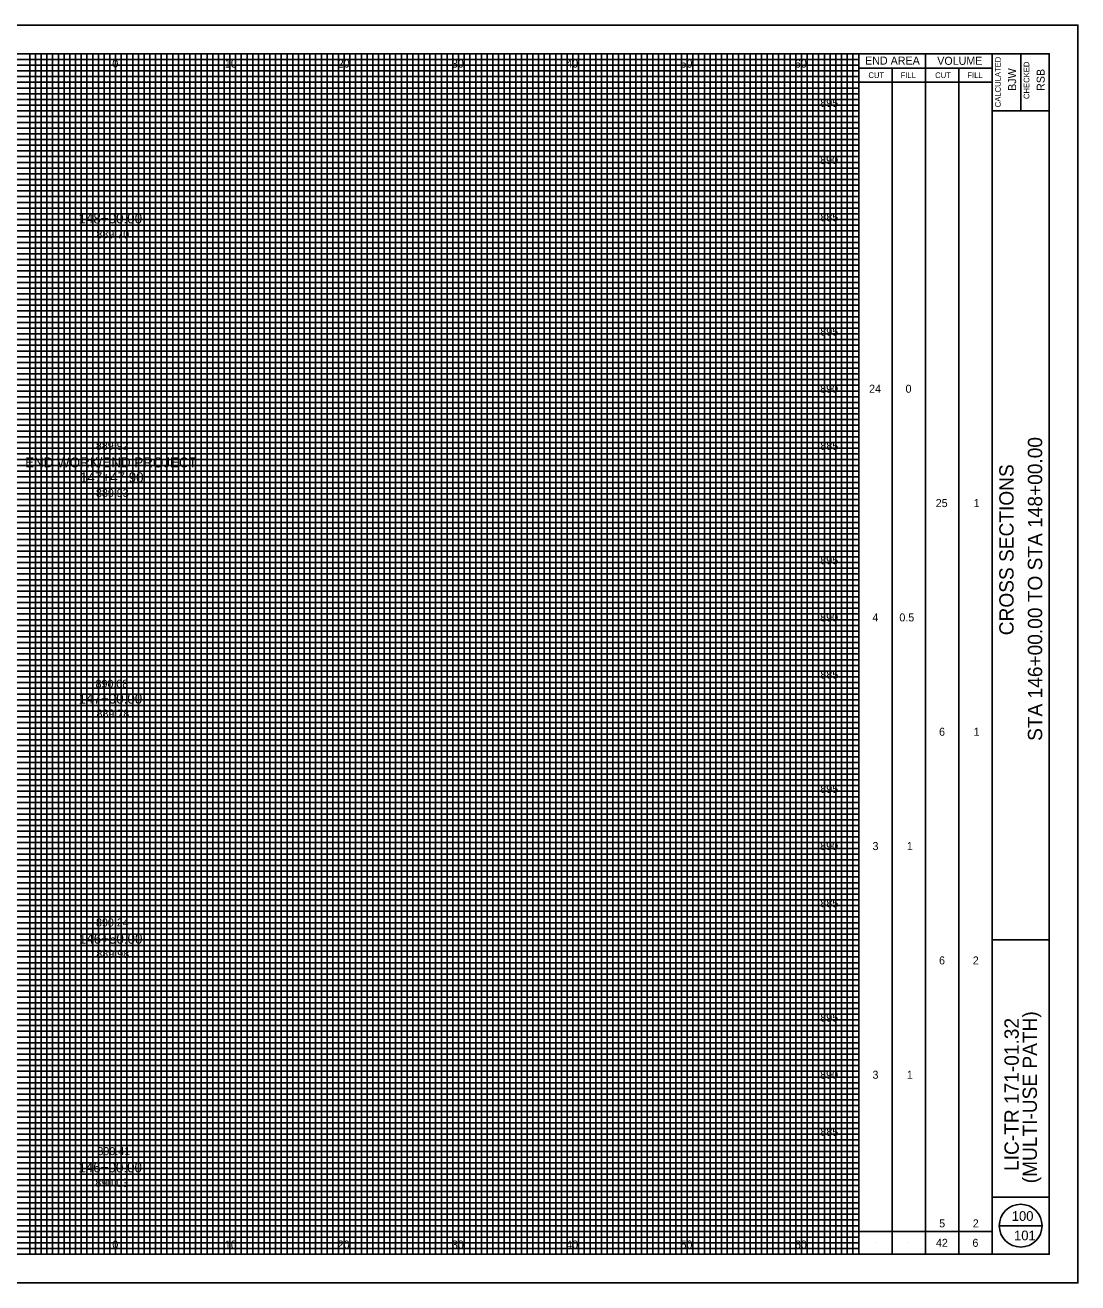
# Model space of a CAD drawing. Extents: x -10 to 160, y -2 to 3672.
# Drawn here: x 67.9 to 160, y 3562.5 to 3672.5 of the extents above; entities that cross this region are included whole.
import ezdxf

# ---------------------------------------------------------------- set-up
doc = ezdxf.new("R2010")
doc.units = 0
for name, color, linetype in [('SH_Border', 7, 'Continuous'), ('SH_Cut_Line', 7, 'Continuous'), ('SH_Data', 7, 'Continuous'), ('SH_Major_Grid_Line', 7, 'Continuous'), ('SH_Minor_Grid_Line', 7, 'Continuous'), ('SH_Text', 7, 'Continuous'), ('TX_P_10', 7, 'Continuous'), ('TX_X_10', 7, 'Continuous')]:
    doc.layers.add(name, color=color, linetype=linetype)

msp = doc.modelspace()

# ---------------------------------------------------------------- linework, layer by layer
at = {"layer": 'SH_Border'}
for p, q in [((152.5, 3565), (152.5, 3670)), ((155, 3670), (155, 3665)), ((152.5, 3665), (157.5, 3665)), ((152.5, 3592.5), (157.5, 3592.5)), ((152.5, 3570), (157.5, 3570))]:
    msp.add_line(p, q, dxfattribs=at)
msp.add_lwpolyline([(0, 3670), (157.5, 3670), (157.5, 3565), (0, 3565)], close=True, dxfattribs=at)
at = {"layer": 'SH_Cut_Line'}
msp.add_lwpolyline([(-10, 3562.5), (160, 3562.5), (160, 3672.5), (-10, 3672.5)], close=True, dxfattribs=at)
at = {"layer": 'SH_Data'}
for p, q in [((140.83, 3565), (140.83, 3670)), ((146.67, 3565), (146.67, 3670)), ((140.83, 3668.75), (152.5, 3668.75)), ((143.75, 3565), (143.75, 3668.75)), ((149.58, 3565), (149.58, 3668.75)), ((140.83, 3667.5), (152.5, 3667.5)), ((153.12, 3567.5), (156.88, 3567.5)), ((140.83, 3567), (152.5, 3567)), ((142.29, 3566), (142.29, 3566)), ((145.21, 3566), (145.21, 3566)), ((148.12, 3566), (148.12, 3566)), ((151.04, 3566), (151.04, 3566))]:
    msp.add_line(p, q, dxfattribs=at)
msp.add_circle((155, 3567.5), 1.87, dxfattribs=at)
at = {"layer": 'SH_Major_Grid_Line'}
for p, q in [((70.83, 3565), (70.83, 3670)), ((75.83, 3565), (75.83, 3670)), ((80.83, 3565), (80.83, 3670)), ((85.83, 3565), (85.83, 3670)), ((90.83, 3565), (90.83, 3670)), ((95.83, 3565), (95.83, 3670)), ((100.83, 3565), (100.83, 3670)), ((105.83, 3565), (105.83, 3670)), ((110.83, 3565), (110.83, 3670)), ((115.83, 3565), (115.83, 3670)), ((120.83, 3565), (120.83, 3670)), ((125.83, 3565), (125.83, 3670)), ((130.83, 3565), (130.83, 3670)), ((135.83, 3565), (135.83, 3670)), ((5.83, 3665), (140.83, 3665)), ((5.83, 3660), (140.83, 3660)), ((5.83, 3655), (140.83, 3655)), ((5.83, 3650), (140.83, 3650)), ((5.83, 3645), (140.83, 3645)), ((5.83, 3640), (140.83, 3640)), ((5.83, 3635), (140.83, 3635)), ((5.83, 3630), (140.83, 3630)), ((5.83, 3625), (140.83, 3625)), ((5.83, 3620), (140.83, 3620)), ((5.83, 3615), (140.83, 3615)), ((5.83, 3610), (140.83, 3610)), ((5.83, 3605), (140.83, 3605)), ((5.83, 3600), (140.83, 3600)), ((5.83, 3595), (140.83, 3595)), ((5.83, 3590), (140.83, 3590)), ((5.83, 3585), (140.83, 3585)), ((5.83, 3580), (140.83, 3580)), ((5.83, 3575), (140.83, 3575)), ((5.83, 3570), (140.83, 3570))]:
    msp.add_line(p, q, dxfattribs=at)
at = {"layer": 'SH_Minor_Grid_Line'}
for p, q in [((68.33, 3565), (68.33, 3670)), ((68.83, 3565), (68.83, 3670)), ((69.33, 3565), (69.33, 3670)), ((69.83, 3565), (69.83, 3670)), ((70.33, 3565), (70.33, 3670)), ((71.33, 3565), (71.33, 3670)), ((71.83, 3565), (71.83, 3670)), ((72.33, 3565), (72.33, 3670)), ((72.83, 3565), (72.83, 3670)), ((73.33, 3565), (73.33, 3670)), ((73.83, 3565), (73.83, 3670)), ((74.33, 3565), (74.33, 3670)), ((74.83, 3565), (74.83, 3670)), ((75.33, 3565), (75.33, 3670)), ((76.33, 3565), (76.33, 3670)), ((76.83, 3565), (76.83, 3670)), ((77.33, 3565), (77.33, 3670)), ((77.83, 3565), (77.83, 3670)), ((78.33, 3565), (78.33, 3670)), ((78.83, 3565), (78.83, 3670)), ((79.33, 3565), (79.33, 3670)), ((79.83, 3565), (79.83, 3670)), ((80.33, 3565), (80.33, 3670)), ((81.33, 3565), (81.33, 3670)), ((81.83, 3565), (81.83, 3670)), ((82.33, 3565), (82.33, 3670)), ((82.83, 3565), (82.83, 3670)), ((83.33, 3565), (83.33, 3670)), ((83.83, 3565), (83.83, 3670)), ((84.33, 3565), (84.33, 3670)), ((84.83, 3565), (84.83, 3670)), ((85.33, 3565), (85.33, 3670)), ((86.33, 3565), (86.33, 3670)), ((86.83, 3565), (86.83, 3670)), ((87.33, 3565), (87.33, 3670)), ((87.83, 3565), (87.83, 3670)), ((88.33, 3565), (88.33, 3670)), ((88.83, 3565), (88.83, 3670)), ((89.33, 3565), (89.33, 3670)), ((89.83, 3565), (89.83, 3670)), ((90.33, 3565), (90.33, 3670)), ((91.33, 3565), (91.33, 3670)), ((91.83, 3565), (91.83, 3670)), ((92.33, 3565), (92.33, 3670)), ((92.83, 3565), (92.83, 3670)), ((93.33, 3565), (93.33, 3670)), ((93.83, 3565), (93.83, 3670)), ((94.33, 3565), (94.33, 3670)), ((94.83, 3565), (94.83, 3670)), ((95.33, 3565), (95.33, 3670)), ((96.33, 3565), (96.33, 3670)), ((96.83, 3565), (96.83, 3670)), ((97.33, 3565), (97.33, 3670)), ((97.83, 3565), (97.83, 3670)), ((98.33, 3565), (98.33, 3670)), ((98.83, 3565), (98.83, 3670)), ((99.33, 3565), (99.33, 3670)), ((99.83, 3565), (99.83, 3670)), ((100.33, 3565), (100.33, 3670)), ((101.33, 3565), (101.33, 3670)), ((101.83, 3565), (101.83, 3670)), ((102.33, 3565), (102.33, 3670)), ((102.83, 3565), (102.83, 3670)), ((103.33, 3565), (103.33, 3670)), ((103.83, 3565), (103.83, 3670)), ((104.33, 3565), (104.33, 3670)), ((104.83, 3565), (104.83, 3670)), ((105.33, 3565), (105.33, 3670)), ((106.33, 3565), (106.33, 3670)), ((106.83, 3565), (106.83, 3670)), ((107.33, 3565), (107.33, 3670)), ((107.83, 3565), (107.83, 3670)), ((108.33, 3565), (108.33, 3670)), ((108.83, 3565), (108.83, 3670)), ((109.33, 3565), (109.33, 3670)), ((109.83, 3565), (109.83, 3670)), ((110.33, 3565), (110.33, 3670)), ((111.33, 3565), (111.33, 3670)), ((111.83, 3565), (111.83, 3670)), ((112.33, 3565), (112.33, 3670)), ((112.83, 3565), (112.83, 3670)), ((113.33, 3565), (113.33, 3670)), ((113.83, 3565), (113.83, 3670)), ((114.33, 3565), (114.33, 3670)), ((114.83, 3565), (114.83, 3670)), ((115.33, 3565), (115.33, 3670)), ((116.33, 3565), (116.33, 3670)), ((116.83, 3565), (116.83, 3670)), ((117.33, 3565), (117.33, 3670)), ((117.83, 3565), (117.83, 3670)), ((118.33, 3565), (118.33, 3670)), ((118.83, 3565), (118.83, 3670)), ((119.33, 3565), (119.33, 3670)), ((119.83, 3565), (119.83, 3670)), ((120.33, 3565), (120.33, 3670)), ((121.33, 3565), (121.33, 3670)), ((121.83, 3565), (121.83, 3670)), ((122.33, 3565), (122.33, 3670)), ((122.83, 3565), (122.83, 3670)), ((123.33, 3565), (123.33, 3670)), ((123.83, 3565), (123.83, 3670)), ((124.33, 3565), (124.33, 3670)), ((124.83, 3565), (124.83, 3670)), ((125.33, 3565), (125.33, 3670)), ((126.33, 3565), (126.33, 3670)), ((126.83, 3565), (126.83, 3670)), ((127.33, 3565), (127.33, 3670)), ((127.83, 3565), (127.83, 3670)), ((128.33, 3565), (128.33, 3670)), ((128.83, 3565), (128.83, 3670)), ((129.33, 3565), (129.33, 3670)), ((129.83, 3565), (129.83, 3670)), ((130.33, 3565), (130.33, 3670)), ((131.33, 3565), (131.33, 3670)), ((131.83, 3565), (131.83, 3670)), ((132.33, 3565), (132.33, 3670)), ((132.83, 3565), (132.83, 3670)), ((133.33, 3565), (133.33, 3670)), ((133.83, 3565), (133.83, 3670)), ((134.33, 3565), (134.33, 3670)), ((134.83, 3565), (134.83, 3670)), ((135.33, 3565), (135.33, 3670)), ((136.33, 3565), (136.33, 3670)), ((136.83, 3565), (136.83, 3670)), ((137.33, 3565), (137.33, 3670)), ((137.83, 3565), (137.83, 3670)), ((138.33, 3565), (138.33, 3670)), ((138.83, 3565), (138.83, 3670)), ((139.33, 3565), (139.33, 3670)), ((139.83, 3565), (139.83, 3670)), ((140.33, 3565), (140.33, 3670)), ((5.83, 3669.5), (140.83, 3669.5)), ((5.83, 3669), (140.83, 3669)), ((5.83, 3668.5), (140.83, 3668.5)), ((5.83, 3668), (140.83, 3668)), ((5.83, 3667.5), (140.83, 3667.5)), ((5.83, 3667), (140.83, 3667)), ((5.83, 3666.5), (140.83, 3666.5)), ((5.83, 3666), (140.83, 3666)), ((5.83, 3665.5), (140.83, 3665.5)), ((5.83, 3664.5), (140.83, 3664.5)), ((5.83, 3664), (140.83, 3664)), ((5.83, 3663.5), (140.83, 3663.5)), ((5.83, 3663), (140.83, 3663)), ((5.83, 3662.5), (140.83, 3662.5)), ((5.83, 3662), (140.83, 3662)), ((5.83, 3661.5), (140.83, 3661.5)), ((5.83, 3661), (140.83, 3661)), ((5.83, 3660.5), (140.83, 3660.5)), ((5.83, 3659.5), (140.83, 3659.5)), ((5.83, 3659), (140.83, 3659)), ((5.83, 3658.5), (140.83, 3658.5)), ((5.83, 3658), (140.83, 3658)), ((5.83, 3657.5), (140.83, 3657.5)), ((5.83, 3657), (140.83, 3657)), ((5.83, 3656.5), (140.83, 3656.5)), ((5.83, 3656), (140.83, 3656)), ((5.83, 3655.5), (140.83, 3655.5)), ((5.83, 3654.5), (140.83, 3654.5)), ((5.83, 3654), (140.83, 3654)), ((5.83, 3653.5), (140.83, 3653.5)), ((5.83, 3653), (140.83, 3653)), ((5.83, 3652.5), (140.83, 3652.5)), ((5.83, 3652), (140.83, 3652)), ((5.83, 3651.5), (140.83, 3651.5)), ((5.83, 3651), (140.83, 3651)), ((5.83, 3650.5), (140.83, 3650.5)), ((5.83, 3649.5), (140.83, 3649.5)), ((5.83, 3649), (140.83, 3649)), ((5.83, 3648.5), (140.83, 3648.5)), ((5.83, 3648), (140.83, 3648)), ((5.83, 3647.5), (140.83, 3647.5)), ((5.83, 3647), (140.83, 3647)), ((5.83, 3646.5), (140.83, 3646.5)), ((5.83, 3646), (140.83, 3646)), ((5.83, 3645.5), (140.83, 3645.5)), ((5.83, 3644.5), (140.83, 3644.5)), ((5.83, 3644), (140.83, 3644)), ((5.83, 3643.5), (140.83, 3643.5)), ((5.83, 3643), (140.83, 3643)), ((5.83, 3642.5), (140.83, 3642.5)), ((5.83, 3642), (140.83, 3642)), ((5.83, 3641.5), (140.83, 3641.5)), ((5.83, 3641), (140.83, 3641)), ((5.83, 3640.5), (140.83, 3640.5)), ((5.83, 3639.5), (140.83, 3639.5)), ((5.83, 3639), (140.83, 3639)), ((5.83, 3638.5), (140.83, 3638.5)), ((5.83, 3638), (140.83, 3638)), ((5.83, 3637.5), (140.83, 3637.5)), ((5.83, 3637), (140.83, 3637)), ((5.83, 3636.5), (140.83, 3636.5)), ((5.83, 3636), (140.83, 3636)), ((5.83, 3635.5), (140.83, 3635.5)), ((5.83, 3634.5), (140.83, 3634.5)), ((5.83, 3634), (140.83, 3634)), ((5.83, 3633.5), (140.83, 3633.5)), ((5.83, 3633), (140.83, 3633)), ((5.83, 3632.5), (140.83, 3632.5)), ((5.83, 3632), (140.83, 3632)), ((5.83, 3631.5), (140.83, 3631.5)), ((5.83, 3631), (140.83, 3631)), ((5.83, 3630.5), (140.83, 3630.5)), ((5.83, 3629.5), (140.83, 3629.5)), ((5.83, 3629), (140.83, 3629)), ((5.83, 3628.5), (140.83, 3628.5)), ((5.83, 3628), (140.83, 3628)), ((5.83, 3627.5), (140.83, 3627.5)), ((5.83, 3627), (140.83, 3627)), ((5.83, 3626.5), (140.83, 3626.5)), ((5.83, 3626), (140.83, 3626)), ((5.83, 3625.5), (140.83, 3625.5)), ((5.83, 3624.5), (140.83, 3624.5)), ((5.83, 3624), (140.83, 3624)), ((5.83, 3623.5), (140.83, 3623.5)), ((5.83, 3623), (140.83, 3623)), ((5.83, 3622.5), (140.83, 3622.5)), ((5.83, 3622), (140.83, 3622)), ((5.83, 3621.5), (140.83, 3621.5)), ((5.83, 3621), (140.83, 3621)), ((5.83, 3620.5), (140.83, 3620.5)), ((5.83, 3619.5), (140.83, 3619.5)), ((5.83, 3619), (140.83, 3619)), ((5.83, 3618.5), (140.83, 3618.5)), ((5.83, 3618), (140.83, 3618)), ((5.83, 3617.5), (140.83, 3617.5)), ((5.83, 3617), (140.83, 3617)), ((5.83, 3616.5), (140.83, 3616.5)), ((5.83, 3616), (140.83, 3616)), ((5.83, 3615.5), (140.83, 3615.5)), ((5.83, 3614.5), (140.83, 3614.5)), ((5.83, 3614), (140.83, 3614)), ((5.83, 3613.5), (140.83, 3613.5)), ((5.83, 3613), (140.83, 3613)), ((5.83, 3612.5), (140.83, 3612.5)), ((5.83, 3612), (140.83, 3612)), ((5.83, 3611.5), (140.83, 3611.5)), ((5.83, 3611), (140.83, 3611)), ((5.83, 3610.5), (140.83, 3610.5)), ((5.83, 3609.5), (140.83, 3609.5)), ((5.83, 3609), (140.83, 3609)), ((5.83, 3608.5), (140.83, 3608.5)), ((5.83, 3608), (140.83, 3608)), ((5.83, 3607.5), (140.83, 3607.5)), ((5.83, 3607), (140.83, 3607)), ((5.83, 3606.5), (140.83, 3606.5)), ((5.83, 3606), (140.83, 3606)), ((5.83, 3605.5), (140.83, 3605.5)), ((5.83, 3604.5), (140.83, 3604.5)), ((5.83, 3604), (140.83, 3604)), ((5.83, 3603.5), (140.83, 3603.5)), ((5.83, 3603), (140.83, 3603)), ((5.83, 3602.5), (140.83, 3602.5)), ((5.83, 3602), (140.83, 3602)), ((5.83, 3601.5), (140.83, 3601.5)), ((5.83, 3601), (140.83, 3601)), ((5.83, 3600.5), (140.83, 3600.5)), ((5.83, 3599.5), (140.83, 3599.5)), ((5.83, 3599), (140.83, 3599)), ((5.83, 3598.5), (140.83, 3598.5)), ((5.83, 3598), (140.83, 3598)), ((5.83, 3597.5), (140.83, 3597.5)), ((5.83, 3597), (140.83, 3597)), ((5.83, 3596.5), (140.83, 3596.5)), ((5.83, 3596), (140.83, 3596)), ((5.83, 3595.5), (140.83, 3595.5)), ((5.83, 3594.5), (140.83, 3594.5)), ((5.83, 3594), (140.83, 3594)), ((5.83, 3593.5), (140.83, 3593.5)), ((5.83, 3593), (140.83, 3593)), ((5.83, 3592.5), (140.83, 3592.5)), ((5.83, 3592), (140.83, 3592)), ((5.83, 3591.5), (140.83, 3591.5)), ((5.83, 3591), (140.83, 3591)), ((5.83, 3590.5), (140.83, 3590.5)), ((5.83, 3589.5), (140.83, 3589.5)), ((5.83, 3589), (140.83, 3589)), ((5.83, 3588.5), (140.83, 3588.5)), ((5.83, 3588), (140.83, 3588)), ((5.83, 3587.5), (140.83, 3587.5)), ((5.83, 3587), (140.83, 3587)), ((5.83, 3586.5), (140.83, 3586.5)), ((5.83, 3586), (140.83, 3586)), ((5.83, 3585.5), (140.83, 3585.5)), ((5.83, 3584.5), (140.83, 3584.5)), ((5.83, 3584), (140.83, 3584)), ((5.83, 3583.5), (140.83, 3583.5)), ((5.83, 3583), (140.83, 3583)), ((5.83, 3582.5), (140.83, 3582.5)), ((5.83, 3582), (140.83, 3582)), ((5.83, 3581.5), (140.83, 3581.5)), ((5.83, 3581), (140.83, 3581)), ((5.83, 3580.5), (140.83, 3580.5)), ((5.83, 3579.5), (140.83, 3579.5)), ((5.83, 3579), (140.83, 3579)), ((5.83, 3578.5), (140.83, 3578.5)), ((5.83, 3578), (140.83, 3578)), ((5.83, 3577.5), (140.83, 3577.5)), ((5.83, 3577), (140.83, 3577)), ((5.83, 3576.5), (140.83, 3576.5)), ((5.83, 3576), (140.83, 3576)), ((5.83, 3575.5), (140.83, 3575.5)), ((5.83, 3574.5), (140.83, 3574.5)), ((5.83, 3574), (140.83, 3574)), ((5.83, 3573.5), (140.83, 3573.5)), ((5.83, 3573), (140.83, 3573)), ((5.83, 3572.5), (140.83, 3572.5)), ((5.83, 3572), (140.83, 3572)), ((5.83, 3571.5), (140.83, 3571.5)), ((5.83, 3571), (140.83, 3571)), ((5.83, 3570.5), (140.83, 3570.5)), ((5.83, 3569.5), (140.83, 3569.5)), ((5.83, 3569), (140.83, 3569)), ((5.83, 3568.5), (140.83, 3568.5)), ((5.83, 3568), (140.83, 3568)), ((5.83, 3567.5), (140.83, 3567.5)), ((5.83, 3567), (140.83, 3567)), ((5.83, 3566.5), (140.83, 3566.5)), ((5.83, 3566), (140.83, 3566)), ((5.83, 3565.5), (140.83, 3565.5))]:
    msp.add_line(p, q, dxfattribs=at)

# ---------------------------------------------------------------- texts
at = {"layer": 'SH_Data'}
for s, height, p in [('END AREA', 0.7, (141.39, 3669.05)), ('VOLUME', 0.7, (147.7, 3669.03)), ('CUT', 0.5, (141.68, 3667.87)), ('FILL', 0.5, (144.5, 3667.87)), ('CUT', 0.5, (147.52, 3667.87)), ('FILL', 0.5, (150.34, 3667.87)), ('100', 0.85, (154.22, 3567.92)), ('101', 0.85, (154.42, 3566.22))]:
    msp.add_text(s, height=height, dxfattribs=at).set_placement(p)
for s, height, p in [('CALCULATED', 0.5, (153.26, 3665.32)), ('BJW', 0.7, (154.6, 3666.75)), ('CHECKED', 0.5, (155.76, 3666.04)), ('RSB', 0.7, (157.1, 3666.75)), ('STA 146+00.00 TO STA 148+00.00', 1.25, (156.88, 3609.9)), ('CROSS SECTIONS', 1.25, (154.38, 3619.14)), ('(MULTI-USE PATH)', 1.25, (156.42, 3571.21)), ('LIC-TR 171-01.32', 1.25, (154.83, 3572.29))]:
    msp.add_text(s, height=height, rotation=90, dxfattribs=at).set_placement(p)
at = {"layer": 'SH_Text'}
for s, height, p in [('0', 0.7, (75.55, 3668.79)), ('10', 0.7, (85.39, 3668.79)), ('20', 0.7, (95.26, 3668.79)), ('30', 0.7, (105.25, 3668.79)), ('40', 0.7, (115.25, 3668.79)), ('50', 0.7, (125.25, 3668.79)), ('60', 0.7, (135.25, 3668.79)), ('895', 0.7, (137.47, 3665.35)), ('890', 0.7, (137.46, 3660.35)), ('148+00.00', 0.875, (72.59, 3655.16)), ('885', 0.7, (137.48, 3655.35)), ('895', 0.7, (137.47, 3645.35)), ('890', 0.7, (137.46, 3640.35)), ('24', 0.7, (141.74, 3640.35)), ('0', 0.7, (144.93, 3640.35)), ('885', 0.7, (137.48, 3635.35)), ('END WORK/END PROJECT', 0.875, (67.92, 3633.82)), ('147+47.90', 0.875, (72.72, 3632.51)), ('25', 0.7, (147.57, 3630.35)), ('1', 0.7, (150.88, 3630.35)), ('895', 0.7, (137.47, 3625.35)), ('890', 0.7, (137.46, 3620.35)), ('4', 0.7, (142.03, 3620.35)), ('0.5', 0.7, (144.39, 3620.35)), ('885', 0.7, (137.48, 3615.35)), ('147+00.00', 0.875, (72.6, 3613.16)), ('6', 0.7, (147.86, 3610.35)), ('1', 0.7, (150.88, 3610.35)), ('895', 0.7, (137.47, 3605.35)), ('890', 0.7, (137.46, 3600.35)), ('3', 0.7, (142.04, 3600.35)), ('1', 0.7, (145.04, 3600.35)), ('885', 0.7, (137.48, 3595.35)), ('146+50.00', 0.875, (72.62, 3592.16)), ('6', 0.7, (147.86, 3590.35)), ('2', 0.7, (150.81, 3590.35)), ('895', 0.7, (137.47, 3585.35)), ('890', 0.7, (137.46, 3580.35)), ('3', 0.7, (142.04, 3580.35)), ('1', 0.7, (145.04, 3580.35)), ('885', 0.7, (137.48, 3575.35)), ('146+00.00', 0.875, (72.58, 3572.16)), ('5', 0.7, (147.87, 3567.35)), ('2', 0.7, (150.81, 3567.35)), ('0', 0.7, (75.55, 3565.5)), ('10', 0.7, (85.39, 3565.5)), ('20', 0.7, (95.26, 3565.5)), ('30', 0.7, (105.25, 3565.5)), ('40', 0.7, (115.25, 3565.5)), ('50', 0.7, (125.25, 3565.5)), ('60', 0.7, (135.25, 3565.5)), ('42', 0.7, (147.59, 3565.65)), ('6', 0.7, (150.78, 3565.65))]:
    msp.add_text(s, height=height, dxfattribs=at).set_placement(p)
at = {"layer": 'TX_P_10'}
for s, p in [('889.92', (74.11, 3635.36)), ('890.08', (74.08, 3614.55)), ('890.24', (74.12, 3593.67)), ('890.41', (74.25, 3573.67))]:
    msp.add_text(s, height=0.7, dxfattribs=at).set_placement(p)
at = {"layer": 'TX_X_10'}
for s, p in [('889.70', (74.15, 3653.86)), ('889.93', (74.12, 3631.23)), ('889.78', (74.16, 3611.94)), ('889.98', (74.15, 3590.92)), ('890.03', (74.06, 3570.9))]:
    msp.add_text(s, height=0.7, dxfattribs=at).set_placement(p)

doc.saveas('drawing.dxf')
